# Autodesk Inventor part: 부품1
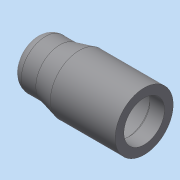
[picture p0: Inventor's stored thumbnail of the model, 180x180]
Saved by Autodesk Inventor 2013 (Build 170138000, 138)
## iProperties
Created: 2019-07
Part Number: 부품1
Material: 일반
Document SubType Name: Modeling
Designer: Administrator
Density: 1 g/cm^3
Author: Administrator
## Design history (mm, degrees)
sketch "스케치1"
  geometry: L1 (-9.347, 2.338)-(15.653, 2.338); L2 (-9.347, -22.662)-(-9.347, 2.338); L3 (35.653, 7.338)-(102.653, 7.338); L4 (102.653, 7.338)-(102.653, -1.662); L5 (-9.347, -22.662)-(60.653, -22.662); L6 (15.653, 2.338)-(35.653, 7.338); L7 (87.653, -1.662)-(102.653, -1.662); L8 (60.653, 1.338)-(87.653, 1.338); L9 (87.653, 1.338)-(87.653, -1.662); L10 (60.653, -22.662)-(60.653, 1.338); 2 further points
  constraints: 20 end point, 4 horizontal, 2 perpendicular, 1 parallel, 1 vertical alignment
  dimensions: "d5" = 25 distance of L2.start L1.start; "d6" = 25 distance from line of L1.end L2; "d7" = 45 distance from line of L3.start L2; "d8" = 112 distance between parallel lines of L2 L4; "d9" = 30 distance of L3.end point (102.653, -22.662); "d22" = 27 distance of L8.start L8.end; "d23" = 24 distance of L5.end L8.start; "d24" = 21 distance between parallel lines of L5 L7; "d25" = 15 distance of L7.start L4.end
revolve "회전1" sketch "스케치1" stored, may be unused: angle "d10" = 90 deg
fillet "모깎기1" dims "d11" = 10
fillet "모깎기2" dims "d26" = 3
hole "구멍1" diameter "d29" = 35; stored, may be unused: countersink angle "d33" = 90 deg, drill point angle "d35" = 0 deg; dims "d30" = 6, "d31" = 42, "d32" = 12, "d34" = 30, "d36" = 10, "d37" = 10
fillet "모깎기3" dims "d38" = 0.3
node "솔리드1"
